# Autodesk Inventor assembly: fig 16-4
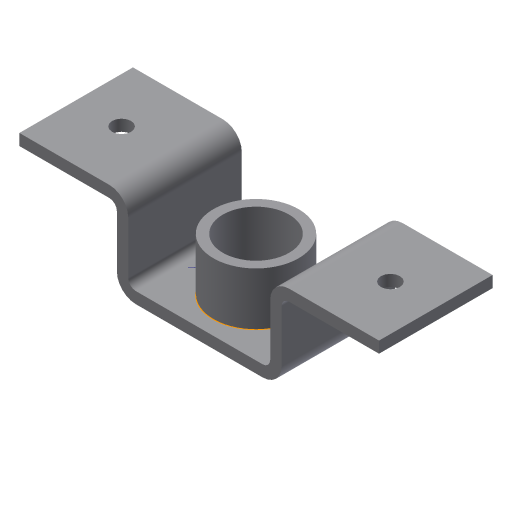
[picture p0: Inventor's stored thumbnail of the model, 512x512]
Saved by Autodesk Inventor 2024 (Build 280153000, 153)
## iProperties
Created: 2004-07
Part Number: fig 16-4
Document SubType Name: Weldment
Designer: CADCIM Technologies
Manufacturer: Standard
Standards Organization: Custom
Author: CADCIM Technologies
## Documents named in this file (3)
- D:\PROJECTS\Project 2023\RESOURCES INVENTOR 2024\RESOURCES INVENTOR 2024\Inventor_2023_Part\Inventor_2024_Part\c16_Inv_2024_prt\fig 16-4.iam
- D:\PROJECTS\Project 2023\RESOURCES INVENTOR 2024\RESOURCES INVENTOR 2024\Inventor_2023_Part\Inventor_2024_Part\c16_Inv_2024_prt\Bracket.ipt
- D:\PROJECTS\Project 2023\RESOURCES INVENTOR 2024\RESOURCES INVENTOR 2024\Inventor_2023_Part\Inventor_2024_Part\c16_Inv_2024_prt\cylinder.ipt
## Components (2 placed, 2 different names)
1. Bracket:1 — Insert:1
2. cylinder:1 — Insert:1
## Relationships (1: Insert 1)
- Insert:1: Bracket:1 ↔ cylinder:1
